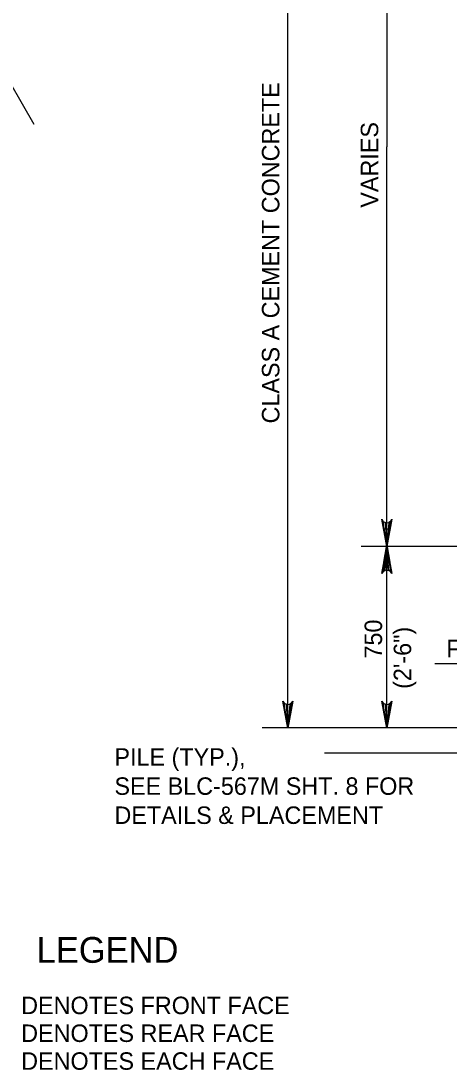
# Model space of a CAD drawing. Extents: x 638340 to 640241, y 295465 to 298435.
# Drawn here: x 638961.4 to 639034.9, y 298134.3 to 298314.5 of the extents above; entities that cross this region are included whole.
import ezdxf

# ---------------------------------------------------------------- set-up
doc = ezdxf.new("R2010")
doc.units = 0
doc.layers.add('3', color=7, linetype='Continuous')

msp = doc.modelspace()

# ---------------------------------------------------------------- linework, layer by layer
at = {"layer": '3'}
for p, q in [((639007.25, 298193.02), (639007.25, 298361.53)), ((639024.25, 298361.53), (639024.25, 298292.89)), ((638951.97, 298316.96), (638963.6, 298296.81)), ((639024.25, 298224.24), (639024.25, 298292.89)), ((639075.45, 298224.24), (639019.82, 298224.24)), ((639024.25, 298193.02), (639024.25, 298224.24)), ((639070.11, 298204.06), (639032.47, 298204.06)), ((639075.19, 298193.1), (639002.82, 298193.1)), ((639087.31, 298188.72), (639013.56, 298188.72))]:
    msp.add_line(p, q, dxfattribs=at)
for points in [[(639024.25, 298224.24), (639023.38, 298228.9), (639023.63, 298228.54), (639023.94, 298228.36), (639024.25, 298228.3), (639024.57, 298228.36), (639024.88, 298228.54), (639025.13, 298228.9), (639024.25, 298224.24), (639024.88, 298228.54), (639024.57, 298228.36), (639024.25, 298224.24), (639024.25, 298228.3), (639023.94, 298228.36), (639024.25, 298224.24), (639023.63, 298228.54)], [(639024.25, 298224.24), (639025.13, 298219.58), (639024.88, 298219.94), (639024.57, 298220.12), (639024.25, 298220.18), (639023.94, 298220.12), (639023.63, 298219.94), (639023.38, 298219.58), (639024.25, 298224.24), (639023.63, 298219.94), (639023.94, 298220.12), (639024.25, 298224.24), (639024.25, 298220.18), (639024.57, 298220.12), (639024.25, 298224.24), (639024.88, 298219.94)], [(639007.25, 298193.02), (639006.37, 298197.68), (639006.62, 298197.32), (639006.94, 298197.13), (639007.25, 298197.08), (639007.56, 298197.13), (639007.87, 298197.32), (639008.12, 298197.68), (639007.25, 298193.02), (639007.87, 298197.32), (639007.56, 298197.13), (639007.25, 298193.02), (639007.25, 298197.08), (639006.94, 298197.13), (639007.25, 298193.02), (639006.62, 298197.32)], [(639024.25, 298193.02), (639023.38, 298197.68), (639023.63, 298197.32), (639023.94, 298197.13), (639024.25, 298197.08), (639024.57, 298197.13), (639024.88, 298197.32), (639025.13, 298197.68), (639024.25, 298193.02), (639024.88, 298197.32), (639024.57, 298197.13), (639024.25, 298193.02), (639024.25, 298197.08), (639023.94, 298197.13), (639024.25, 298193.02), (639023.63, 298197.32)]]:
    msp.add_lwpolyline(points, dxfattribs=at)
for points in [[(639024.74, 298227.19), (639023.76, 298227.19), (639024.25, 298224.24)], [(639024.74, 298221.55), (639023.76, 298221.55), (639024.25, 298224.5)], [(639024.74, 298221.55), (639023.76, 298221.55), (639024.25, 298224.5)]]:
    msp.add_lwpolyline(points, close=True, dxfattribs=at)

# ---------------------------------------------------------------- texts
for s, height, p in [('CLASS A CEMENT CONCRETE', 3.0001, (639005.79, 298245.37)), ('VARIES', 3, (639022.77, 298282.44)), ('750', 3, (639023.43, 298204.98)), ('(2\'-6")', 3, (639028.43, 298199.77))]:
    msp.add_text(s, height=height, rotation=90, dxfattribs=at).set_placement(p)
for s, height, p in [('F1604 (F504)', 3.0001, (639034.47, 298205.2)), ('PILE (TYP.), ', 3.0001, (638977.46, 298186.56)), ('SEE BLC-567M SHT. 8 FOR', 3.0001, (638977.46, 298181.56)), ('DETAILS & PLACEMENT  ', 3.0001, (638977.46, 298176.56)), ('LEGEND', 4.429, (638964.1, 298152.7)), ('DENOTES FRONT FACE', 3.0001, (638961.44, 298143.88)), ('DENOTES REAR FACE', 3.0001, (638961.44, 298139.1)), ('DENOTES EACH FACE', 3.0001, (638961.44, 298134.32))]:
    msp.add_text(s, height=height, dxfattribs=at).set_placement(p)

doc.saveas('drawing.dxf')
